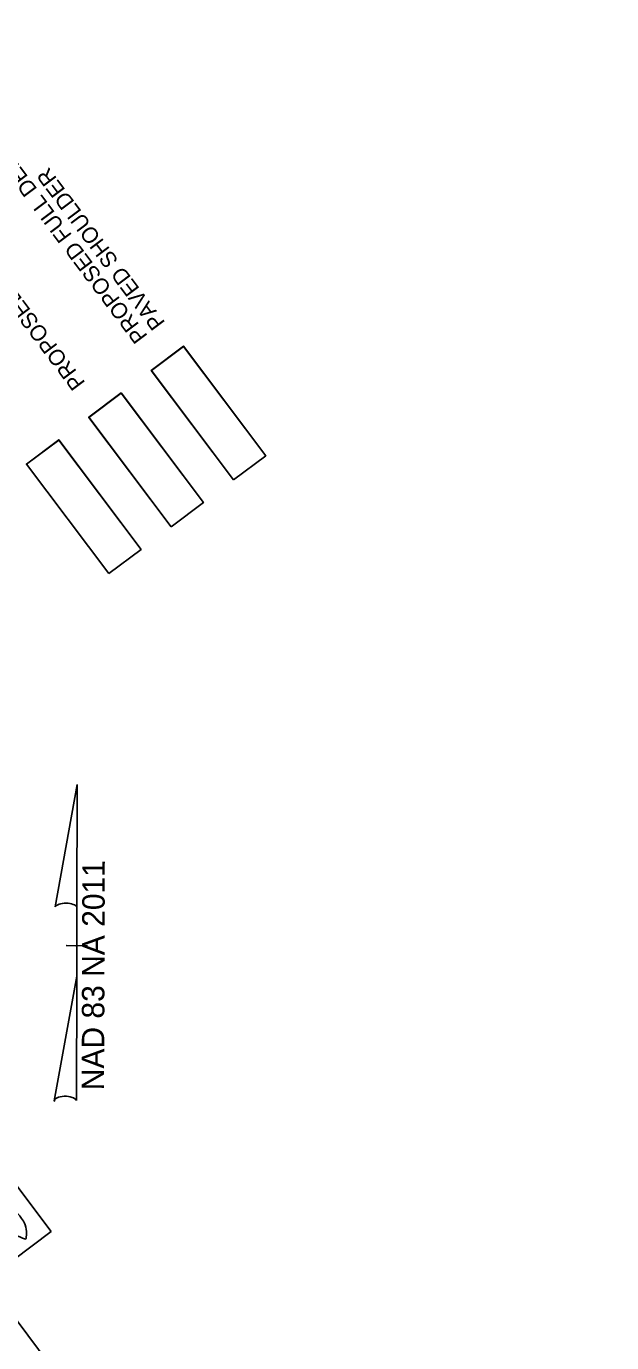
# Model space of a CAD drawing. Extents: x 1265100 to 1267089, y 771887 to 773927.
# Drawn here: x 1265500.7 to 1265722.3, y 772893.1 to 773391.7 of the extents above; entities that cross this region are included whole.
import ezdxf

# ---------------------------------------------------------------- set-up
doc = ezdxf.new("R2010")
doc.units = 0
for name, color, linetype in [('Exist Roads EOT', 7, 'Continuous'), ('Exist Utilities Power Pole Cogo Elevation', 7, 'Continuous'), ('Exist Utilities Sanitary Sewer Manhole Cogo Elevation', 7, 'Continuous'), ('Prop Conc 1ft 6in Curb and Gutter', 7, 'Continuous'), ('Prop Conc Expressway Gutter', 7, 'Continuous'), ('Prop Horizontal Alignment Direction Label', 7, 'Continuous'), ('Typical Terminator CELL', 7, 'Continuous')]:
    doc.layers.add(name, color=color, linetype=linetype)

msp = doc.modelspace()

# ---------------------------------------------------------------- linework, layer by layer
at = {"layer": 'Exist Roads EOT'}
msp.add_lwpolyline([(1265579.14, 773219.86), (1265591.37, 773229.05), (1265560.28, 773270.45), (1265548.05, 773261.26)], close=True, dxfattribs=at)
at = {"layer": 'Exist Utilities Power Pole Cogo Elevation'}
for p, q in [((1265511.62, 773058.12), (1265519.98, 773104.44)), ((1265520.03, 773104.44), (1265519.86, 773056.64)), ((1265520.03, 773104.44), (1265519.98, 773104.44)), ((1265520.03, 773104.44), (1265519.98, 773104.44)), ((1265519.78, 773031.84), (1265519.87, 773058.04)), ((1265519.86, 773056.64), (1265519.87, 773057.99)), ((1265515.82, 773043.45), (1265515.77, 773043.45)), ((1265519.37, 773043.44), (1265515.82, 773043.45)), ((1265515.87, 773043.45), (1265523.87, 773043.43)), ((1265519.78, 773031.84), (1265511.27, 772984.62)), ((1265519.67, 772984.79), (1265519.78, 773031.84))]:
    msp.add_line(p, q, dxfattribs=at)
msp.add_lwpolyline([(1265510.12, 772935.14), (1265390, 773095.1), (1265361.13, 773073.42), (1265481.26, 772913.47)], close=True, dxfattribs=at)
for centre, start_param, end_param in [((1265515.75, 773057.61), 0.216388, 2.908219), ((1265515.51, 772984.44), 0.201328, 3.141593)]:
    msp.add_ellipse(centre, major_axis=(4.23, -0.04), ratio=0.461098, start_param=start_param, end_param=end_param, dxfattribs=at)
msp.add_open_spline([(1265493.53, 772936.86), (1265493.87, 772936.42), (1265493.91, 772935.85), (1265493.2, 772935.06), (1265493.2, 772935.06), (1265500.56, 772932.19), (1265500.56, 772932.19), (1265501.06, 772935.16), (1265500.11, 772938.58), (1265498.42, 772940.81), (1265497.99, 772941.39), (1265497.6, 772941.8), (1265497.02, 772942.32), (1265497.02, 772942.32), (1265484.98, 772943.83), (1265484.98, 772943.83), (1265484.98, 772943.83), (1265479.95, 772940.04), (1265479.95, 772940.04), (1265479.95, 772940.04), (1265490.33, 772936.13), (1265490.33, 772936.13), (1265492.22, 772937.55), (1265493.07, 772937.48), (1265493.53, 772936.86)], degree=3, dxfattribs=at)
msp.add_open_spline([(1265493.53, 772936.86), (1265493.87, 772936.42), (1265493.91, 772935.85), (1265493.2, 772935.06), (1265493.2, 772935.06), (1265500.56, 772932.19), (1265500.56, 772932.19), (1265501.06, 772935.16), (1265500.11, 772938.58), (1265498.42, 772940.81), (1265497.99, 772941.39), (1265497.6, 772941.8), (1265497.02, 772942.32), (1265497.02, 772942.32), (1265484.98, 772943.83), (1265484.98, 772943.83), (1265484.98, 772943.83), (1265479.95, 772940.04), (1265479.95, 772940.04), (1265479.95, 772940.04), (1265490.33, 772936.13), (1265490.33, 772936.13), (1265492.22, 772937.55), (1265493.07, 772937.48), (1265493.53, 772936.86)], degree=3, dxfattribs=at)
at = {"layer": 'Exist Utilities Sanitary Sewer Manhole Cogo Elevation'}
msp.add_lwpolyline([(1265531.91, 773184.39), (1265544.14, 773193.57), (1265513.05, 773234.97), (1265500.82, 773225.79)], close=True, dxfattribs=at)
at = {"layer": 'Prop Conc 1ft 6in Curb and Gutter'}
for points in [[(1265579.14, 773219.86), (1265591.37, 773229.05), (1265560.21, 773270.55), (1265547.98, 773261.36)], [(1265555.52, 773202.13), (1265567.75, 773211.31), (1265536.59, 773252.81), (1265524.36, 773243.63)], [(1265531.91, 773184.39), (1265544.14, 773193.57), (1265512.97, 773235.08), (1265500.74, 773225.89)]]:
    msp.add_lwpolyline(points, close=True, dxfattribs=at)
at = {"layer": 'Prop Conc Expressway Gutter'}
msp.add_lwpolyline([(1265555.52, 773202.13), (1265567.75, 773211.31), (1265536.66, 773252.71), (1265524.43, 773243.53)], close=True, dxfattribs=at)
at = {"layer": 'Typical Terminator CELL'}
msp.add_lwpolyline([(1266289.35, 772153.62), (1266298.14, 772160.44), (1266307.8, 772184.21), (1266331.91, 772215.31), (1266332.35, 772261.45), (1266387.5, 772467.54), (1266710.25, 772749.07), (1266813.62, 772836.44), (1266224.27, 773631.5), (1266145.65, 773582.41), (1265981.26, 773779.69), (1265375.94, 773334.64), (1265484.1, 773191.06), (1265496.18, 773177.78), (1265368.96, 773080.53), (1265370.53, 773071.49), (1265889.02, 772374.44), (1265992.81, 772219.74), (1266130.48, 772035.91)], close=True, dxfattribs=at)

# ---------------------------------------------------------------- texts
at = {"layer": 'Exist Utilities Power Pole Cogo Elevation'}
msp.add_text('NAD 83 NA 2011', height=8.5, rotation=89.8059, dxfattribs=at).set_placement((1265530.15, 772988.66))
at = {"layer": 'Prop Horizontal Alignment Direction Label'}
for s, p in [('PROPOSED 4" CONCRETE SIDEWALK', (1265523.23, 773256.68)), ('PROPOSED FULL DEPTH', (1265546.85, 773274.41)), ('PAVED SHOULDER', (1265553.47, 773279.47))]:
    msp.add_text(s, height=6, rotation=126.9057, dxfattribs=at).set_placement(p)

doc.saveas('drawing.dxf')
